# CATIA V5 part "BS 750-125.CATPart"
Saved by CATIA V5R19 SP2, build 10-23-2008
Part number: BS 750-125
Bounding box of the stored display mesh (mm): x -22.494 to 22.494, y -22.494 to 22.494, z 0 to 282
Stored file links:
  C:\Users\Bora\Desktop\3D Katı model\BS serisi\BS 750\BS 750-125.CATPart
  C:\Program Files\Dassault Systemes\B19\intel_a\reffiles\standard\MetricThickPitch.txt
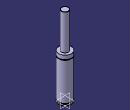
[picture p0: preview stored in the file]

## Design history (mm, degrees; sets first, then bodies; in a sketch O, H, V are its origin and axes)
Body1 (main body)
  Sketch1 on yz-plane, origin (0, 0, 0), H (0, 1, 0), V (0, 0, 1)
    point P3 (12.5, 281)
    point P5 (12.5, 281)
    point P7 (22.5, 142.5)
    point P8 (22.5, 140.5)
    point P12 (22.5, 140.5)
    point P13 (22.5, 142.5)
    line L1 (22.5, 0) -> (22.5, 4)
    line L2 (12.5, 281) -> (12.5, 156)
    arc A1 centre (11.5, 281) radius 1 from (12.5, 281) to (11.5, 282) ccw
    arc A2 centre (22.5, 141.5) radius 1 from (22.5, 142.5) to (22.5, 140.5) ccw
    line L3 (20, 7.5) -> (20, 4)
    line L4 (22.5, 7.5) -> (22.5, 140.5)
    line L5 (22.5, 142.5) -> (22.5, 156)
    line L6 (11.5, 282) -> (0, 282)
    point P15 (0, 282)
    line L7 (12.5, 156) -> (22.5, 156)
    line L8 (0, 0) -> (22.5, 0)
    line L9 (20, 7.5) -> (22.5, 7.5)
    line L10 (20, 4) -> (22.5, 4)
    coincidence: P15 V, P3 P5, P7 P13, P8 P12
    tangency: L6 A1
    horizontal: L7 H, L8 H, L9 H, L10 H
  Shaft1: profile Sketch1, axis Sketch1.V, angle 360
  Sketch2 on face of Shaft1 from Sketch1.L8, origin (0, 0, 0), H (1, 0, 0), V (0, -1, 0)
    point P1 (10, 0)
    distance P1 V = 10
  Hole1: placed by Sketch2, at (10, 0, 0) direction (0, 0, 1), diameter 6.647, depth 4, threaded "M8", thread diameter 8, thread depth 4, pitch 1.25
  CircPattern1: of Hole1, instances 2, angular step 180, axis from xy-plane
